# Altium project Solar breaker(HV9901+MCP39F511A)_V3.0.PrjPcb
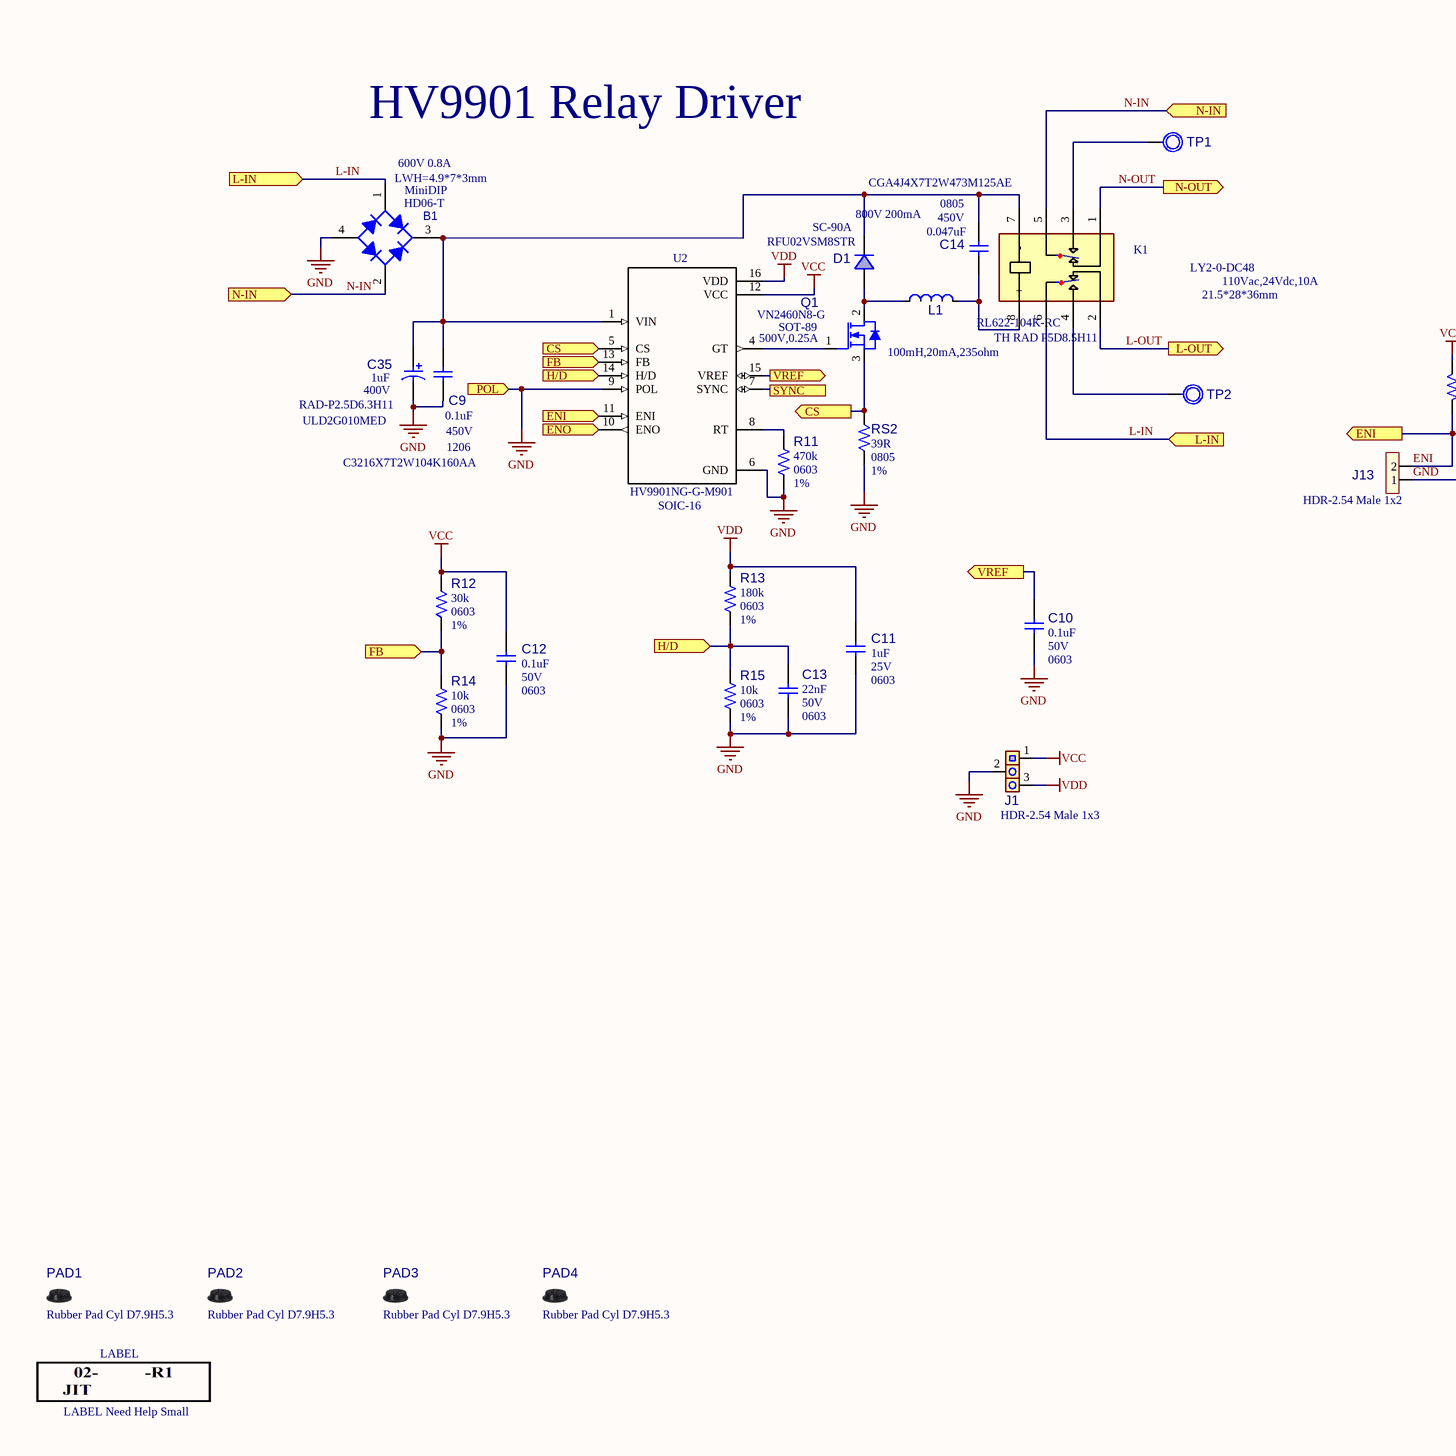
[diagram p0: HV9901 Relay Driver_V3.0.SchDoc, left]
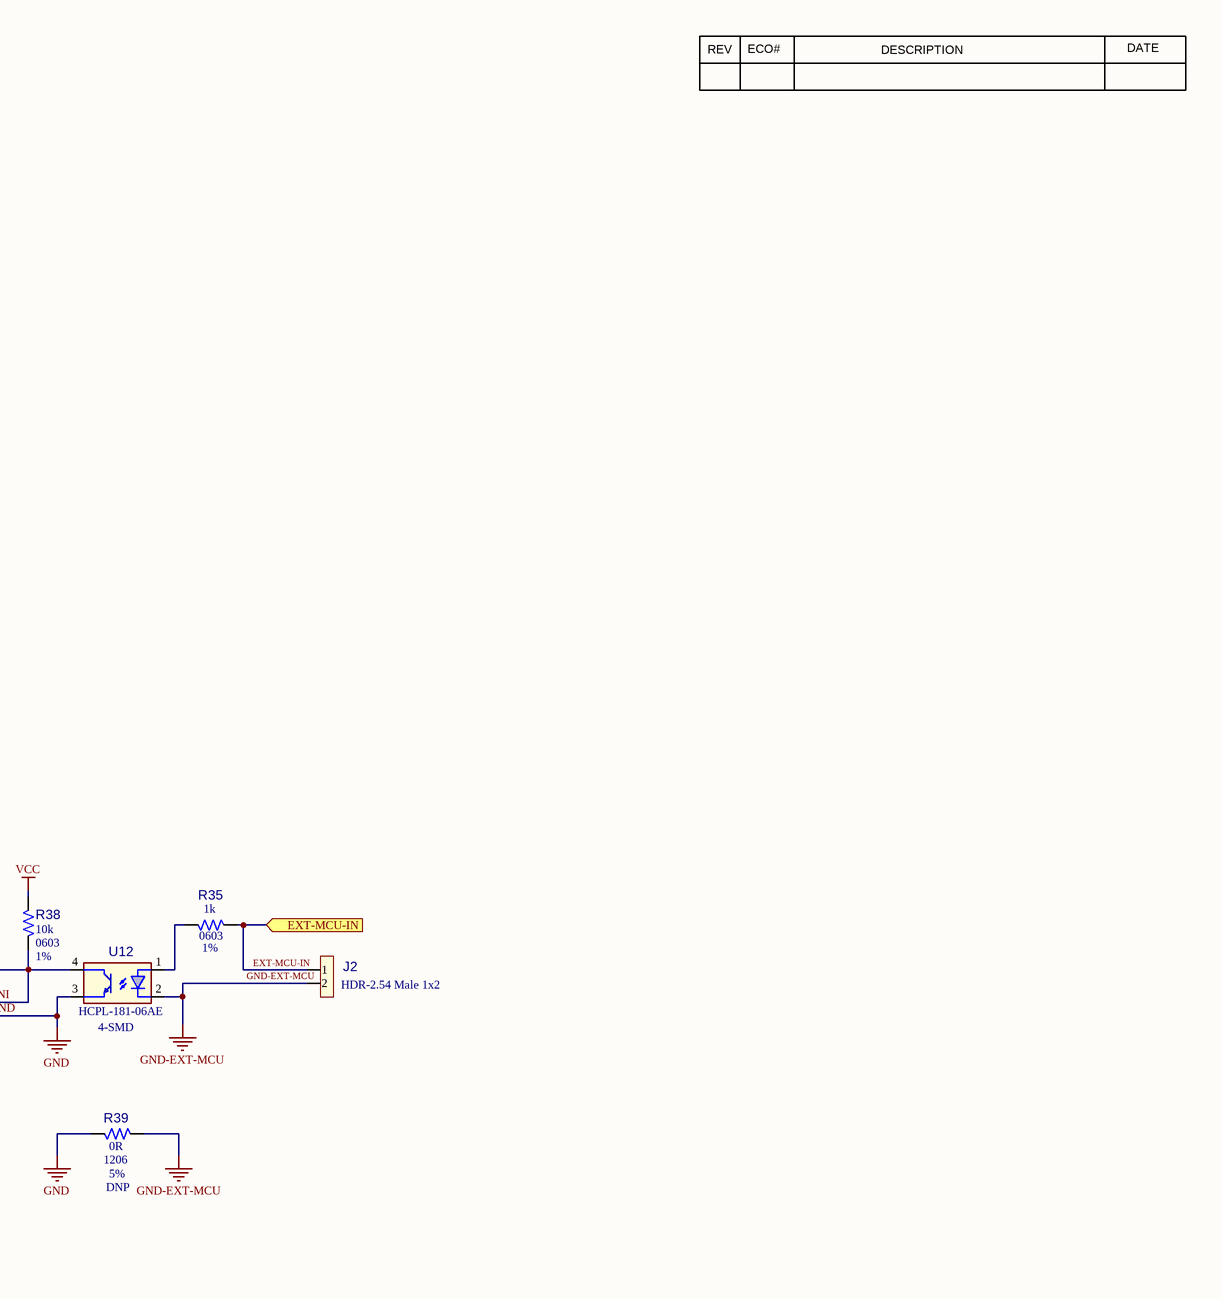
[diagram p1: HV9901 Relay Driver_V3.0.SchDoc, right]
ProjectRevisionART: 3; ProjectPCBNumber: Solar breaker(HV9901+MCP39F511A); ProjectRevisionAssy: 3; ProjectPCBAssyNumber: Solar breaker(HV9901+MCP39F511A)
2 sheets, 133 parts. Net scope: flat (ports and power ports of the same name join across sheets).
Board file: Solar breaker(HV9901+MCP39F511A)_V3.0.PcbDoc
Sheets:
  HV9901 Relay Driver_V3.0.SchDoc
  MCP39F511A Power Monitoring_V3.0.SchDoc

## Sheet HV9901 Relay Driver_V3.0.SchDoc
size A3; CompanyName: Microchip Technology Inc.; Organization: Microchip Technology; Address1: 2355 West Chandler Blvd.; Address2: Chandler, AZ  85224; Address4: USA; SheetTitle: **; PageSetup: Record=PageOptions¦CenterHorizontal=True¦CenterVertical=True¦PrintScale=0.52¦XCorrection=1.00¦YCorrection=1.00¦PrintKind=1¦BorderSize=5000000¦LeftOffset=0¦BottomOffset=0¦Orientation=2¦PaperLength=1000¦PaperWidth=1000¦Scale=100¦PaperSource=7¦PrintQuality=-3¦MediaType=1¦DitherType=10¦PrintScaleMode=1¦PaperKind=A4¦PaperIndex=9

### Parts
B1  B?  [HD01-HD06,DIODES,BRIDGE RECTIFIER]  (value not drawn)
C9  value 0.1uF  Voltage: 450V  Package: 1206  [CAP_C_1206]  (hidden comment: Capacitor NP)
C10  value 0.1uF  Voltage: 50V  Package: 0603  [CAP_C_0603]  (hidden comment: Capacitor NP)
C11  value 1uF  Voltage: 25V  Package: 0603  [CAP_C_0603]  (hidden comment: Capacitor NP)
C12  value 0.1uF  Voltage: 50V  Package: 0603  [CAP_C_0603]  (hidden comment: Capacitor NP)
C13  value 22nF  Voltage: 50V  Package: 0603  [CAP_C_0603]  (hidden comment: Capacitor NP)
C14  value 0.047uF  Voltage: 450V  Package: 0805  [CAP_C_0805]  (hidden comment: Capacitor NP)
C35  value 1uF  Voltage: 400V  Package: RAD-P2.5D6.3H11  [CAP_RAD_P2.5D6.3H11.2]  (hidden comment: Capacitor POL)
D1  value RFU02VSM8STR  [SC-90A]  (hidden comment: Diode Single)
J1  value HDR-2.54 Male 1x3  [HDR_M_2.54_1x3]  (hidden comment: Header 1x3)
J2  value HDR-2.54 Male 1x2  [HDR_M_2.54_1x2]  (hidden comment: Header 1x2)
J13  value HDR-2.54 Male 1x2  [HDR_M_2.54_1x2]  (hidden comment: Header 1x2)
K1  RELAY_LY2-0-DC48_DPDT 10A 48V,2Poles,THD  [RELAY_LY2-0-DC48_DPDT 10A 48V,2Poles,THD]  (value not drawn)
L1  value 100mH,20mA,235ohm  [IND_WE-TI-8055_P5D8.5H5.5]  (hidden comment: Inductor)
LABEL  value LABEL Need Help Small  [LABEL_Need_Help_Small]  (hidden comment: LABEL_Need_Help_Small)
PAD1  value Rubber Pad Cyl D7.9H5.3  [BUMP_3M_SJ61A11_CYLINDRICAL_BLACK_D7.9H5.3]  (hidden comment: Rubber Pad Cylindrical)
PAD2  value Rubber Pad Cyl D7.9H5.3  [BUMP_3M_SJ61A11_CYLINDRICAL_BLACK_D7.9H5.3]  (hidden comment: Rubber Pad Cylindrical)
PAD3  value Rubber Pad Cyl D7.9H5.3  [BUMP_3M_SJ61A11_CYLINDRICAL_BLACK_D7.9H5.3]  (hidden comment: Rubber Pad Cylindrical)
PAD4  value Rubber Pad Cyl D7.9H5.3  [BUMP_3M_SJ61A11_CYLINDRICAL_BLACK_D7.9H5.3]  (hidden comment: Rubber Pad Cylindrical)
Q1  value VN2460N8-G  Package: SOT-89  [SOT-89-3]  (hidden comment: Transistor MOS-N GDS)
R11  value 470k  Package: 0603  Tolerance: 1%  [RES_C_0603]  (hidden comment: Resistor)
R12  value 30k  Package: 0603  Tolerance: 1%  [RES_C_0603]  (hidden comment: Resistor)
R13  value 180k  Package: 0603  Tolerance: 1%  [RES_C_0603]  (hidden comment: Resistor)
R14  value 10k  Package: 0603  Tolerance: 1%  [RES_C_0603]  (hidden comment: Resistor)
R15  value 10k  Package: 0603  Tolerance: 1%  [RES_C_0603]  (hidden comment: Resistor)
R35  value 1k  Package: 0603  Tolerance: 1%  [RES_C_0603]  (hidden comment: Resistor)
R38  value 10k  Package: 0603  Tolerance: 1%  [RES_C_0603]  (hidden comment: Resistor)
R39  value 0R  Package: 1206  [RES_C_1206]  (hidden comment: Resistor)
RS2  value 39R  Package: 0805  Tolerance: 1%  [RES_C_0805]  (hidden comment: Resistor)
TP1  Test Point  [CON_TP_TH_V_WHT_KEC_5002]  (value not drawn)
TP2  Test Point  [CON_TP_TH_V_WHT_KEC_5002]  (value not drawn)
U2  HV9901NG-G-M901  [*SOIC127P600X175-14N]
U12  value HCPL-181-06AE  Package: 4-SMD  [4-SMD_200mil]  (hidden comment: Photocoupler Transistor Out)

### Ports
CS (in), CS (out), ENI (in), ENI (out), ENO (in), EXT-MCU-IN (in), FB (in), H/D (in), L-IN (in), L-OUT (out), N-IN (in), N-OUT (out), POL (in), SYNC (in), VREF (out)

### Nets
GND: B1.4(C) C9.1 C10.1 C11.2 C12.2 C13.1 C35.2 J1.2 J13.1 R11.1 R14.1 R15.1 R39.2 RS2.1 U2.6(GND) U2.9(POL) U12.3(Emitter) ; port POL
GND-EXT-MCU: J2.2 R39.1 U12.2(Cathode)
VCC: C12.1 J1.1 R12.2 R38.2 U2.12(VCC)
VDD: C11.1 J1.3 R13.2 U2.16(VDD)
ENI: J13.2 R38.1 U2.11(ENI) U12.4(Collector) ; port ENI
EXT-MCU-IN: J2.1 R35.1 ; port EXT-MCU-IN
L-IN: B1.1(K) K1.6 ; port L-IN
L-OUT: K1.2 ; port L-OUT
N-IN: B1.2(A) K1.5 ; port N-IN
N-OUT: K1.1 ; port N-OUT
NetB1_3: B1.3(C) C9.2 C14.2 C35.1 D1.2(K) K1.7(-) U2.1(VIN)
NetC10_2: C10.2 U2.15(VREF) ; port VREF
NetC13_2: C13.2 R13.1 R15.2 U2.14(H/D) ; port H/D
NetC14_1: C14.1 K1.8(+) L1.2(F)
NetD1_1: D1.1(A) L1.1(S) Q1.2(D)
NetK1_3: K1.3 TP1.1
NetK1_4: K1.4 TP2.1
NetQ1_1: Q1.1(G) U2.4(GT)
NetQ1_3: Q1.3(S) RS2.2 U2.5(CS) ; port CS
NetR11_2: R11.2 U2.8(RT)
NetR12_1: R12.1 R14.2 U2.13(FB) ; port FB
NetR35_2: R35.2 U12.1(Anode)
NetU2_10: U2.10(ENO) ; port ENO

Not connected (* = marked no-connect by the designer): U2 7(SYNC)

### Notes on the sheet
- REV
- ECO#
- DESCRIPTION
- DATE
- HV9901 Relay Driver
- (near B1) LWH=4.9*7*3mm
- (near B1) 600V 0.8A
- (near B1) HD06-T
- (near B1) MiniDIP
- (near D1) 800V 200mA
- CGA4J4X7T2W473M125AE
- (near K1) LY2-0-DC48
- (near K1) 110Vac,24Vdc,10A
- 500V,0.25A
- (near L1) RL622-104K-RC
- TH RAD P5D8.5H11
- (near K1) 21.5*28*36mm
- ULD2G010MED
- C3216X7T2W104K160AA
- (near U2) SOIC-16
- (near R39) DNP
- (near R39) 5%

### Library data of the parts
C9 = CAP1426: Capacitor; Manufacturer 1: Johanson Dielectrics Inc; Manufacturer Part Number 1: 501R18W223KV4E; Description_: CAP CER 0.022uF 500V 10% X7R SMD 1206; Dev Tools Status: Production; Tolerance: 10%; Type: Ceramic; Owner: Jamus Griego; Populated: YES
C10-C13 = CAP0012: Capacitor; Manufacturer 1: Cal-Chip; Manufacturer Part Number 1: GMC10Y5V104Z25NTLF; Description_: CAP CER 0.1uF 25V 20% Y5V SMD 0603; Dev Tools Status: Production; Tolerance: 20%; Temperature Coeffcient: Y5V; Type: Ceramic; Populated: Yes
C14 = CAP2158: Capacitor; Manufacturer 1: TDK Corporation; Manufacturer Part Number 1: CGA4F4X7T2W103M085AE; Description_: CAP CER 10000pF 450V 10% X7T SMD 0805; Dev Tools Status: Design; Tolerance: 10%; Type: Ceramic; Owner: Cristian Papuc; Populated: YES; Temperature Coeffcient: X7T
C35 = CAP1007: Capacitor
D1 = DIODE1422: Manufacturer 1: Panasonic; Manufacturer Part Number 1: DA2JF2300L; Description_: DIO DA2JF2300L SWITCHING 1.25V 0.3A 300V SC-90A; Dev Tools Status: Design; Type: Rectifier Single; Forward Current: 0.3A; Populated: YES; Owner: Iulian Margarit; Reverse Current: 1uA; Reverse Voltage: 300V
J1 = CON1105: Manufacturer 1: FCI; Manufacturer Part Number 1: 68000-103HLF; Description_: CON HDR-2.54 Male 1x3 Gold 5.84MH TH VERT; Dev Tools Status: Production; Owner: Bogdan P (M91398); Populated: Yes
J2 J13 = CON1108: Manufacturer 1: FCI; Manufacturer Part Number 1: 77311-118-02LF; Description_: CON HDR-2.54 Male 1x2 Gold 5.84MH TH VERT; Dev Tools Status: Production; Owner: Bogdan P (M91398); Populated: Yes
L1 = IND1323: Manufacturer 1: Wurth Electronics Inc; Manufacturer Part Number 1: 7447412681; Description_: INDUCTOR 680uH 330mA 10% TH RAD P5D8.5H5.5; Dev Tools Status: Design; Owner: Catalin Modoran; DCR: 4R; Saturation Current: 350mA; RMS Current: 330mA; Test Frequency: 1kHz; Populated: YES
LABEL = 08-00028: Description_: LABEL, ASSY W/REV LEVEL (SMALL MODULES) PER MTS-0002; Dev Tools Status: Production; Populated: MECH
PAD1-PAD4 = MISC1024: Manufacturer 1: 3M; Manufacturer Part Number 1: SJ61A11; Description_: MECH HW RUBBER PAD CYLINDRICAL D7.9 H5.3 BLACK; Dev Tools Status: Production; Owner: Bogdan Popescu; Populated: MECH
Q1 = TRA1253: Transistor MOS; Manufacturer 1: Microchip Technology; Description_: TRANS FET N-CH VN2460N8-G 600V 200mA 1.6W SOT-89; Dev Tools Status: Design; Type: FET; Current: 200mA; Drain to Source Voltage: 600V; Gate to Source Voltage: 20V; Power: 1.6W; Owner: Cristian Papuc; Populated: YES
R11-R15 R35 R38 = RSMT0138: Manufacturer 1: Panasonic; Manufacturer Part Number 1: ERJ-3EKF1001V; Description_: RES TKF 1k 1% 1/10W SMD 0603; Dev Tools Status: Production; Voltage: 75V; Temperature Coeffcient: 100ppm/C; Power: 1/10W; Populated: Yes
R39 = RES2320: Manufacturer 1: Panasonic Electronic Components; Manufacturer Part Number 1: ERJ-8GEY0R00V; Description_: RES TKF 0R SMD 1206 AEC-Q200; Dev Tools Status: Design; Populated: YES; Current: 2A; Owner: Gabor Bihari
RS2 = RSMT0248: Manufacturer 1: Stackpole Electronics Inc; Manufacturer Part Number 1: RMCF-1/10-39-1%; Description_: RES TKF 39R 1% 1/8W SMD 0805; Dev Tools Status: Production; Voltage: 150V; Temperature Coeffcient: 100ppm/C; Power: 1/8W; Populated: Yes
TP1 TP2 = MISC0028: Manufacturer 1: Keystone; Manufacturer Part Number 1: 5002; Value: TP LOOP White; Description_: MISC, TEST POINT MULTI PURPOSE MINI WHITE; Dev Tools Status: Production
U2 = HV9901NG-G-M901: HV9901 Series 10 to 450V 1 mA 750 mW Universal Relay Driver - SOIC-16N; MF: Microchip
U12 = IC1119: Photocoupler; Manufacturer 1: Avago Technologies; Manufacturer Part Number 1: HCPL-181-00CE; MCHP-ID: IC1119; Description_: IC PHOTO HCPL-181 4-SMD; Dev Tools Status: Production; Owner: Bogdan P (M91398); Populated: Yes

## Sheet MCP39F511A Power Monitoring_V3.0.SchDoc
size A3; CompanyName: Microchip Technology Inc.; Organization: Microchip Technology; Address1: 2355 West Chandler Blvd.; Address2: Chandler, AZ  85224; Address4: USA; SheetTitle: **; PageSetup: Record=PageOptions¦CenterHorizontal=True¦CenterVertical=True¦PrintScale=0.52¦XCorrection=1.00¦YCorrection=1.00¦PrintKind=1¦BorderSize=5000000¦LeftOffset=0¦BottomOffset=0¦Orientation=2¦PaperLength=1000¦PaperWidth=1000¦Scale=100¦PaperSource=7¦PrintQuality=-3¦MediaType=1¦DitherType=10¦PrintScaleMode=1¦PaperKind=A4¦PaperIndex=9
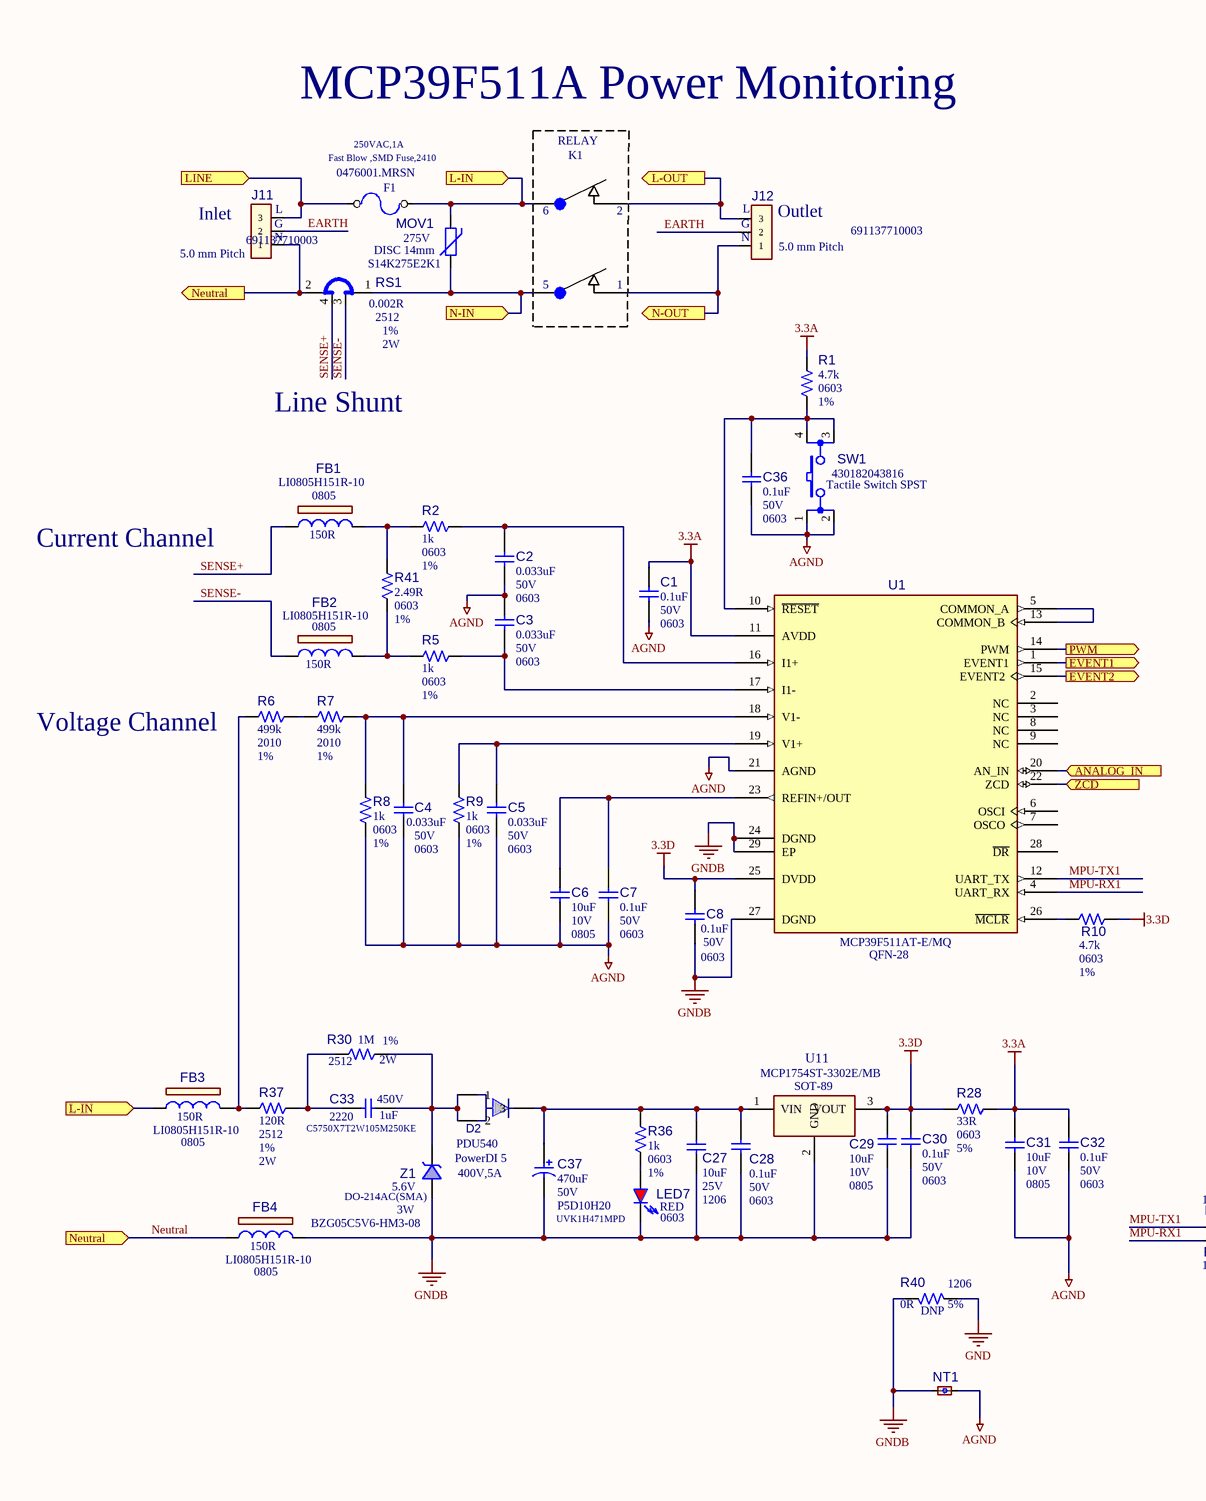
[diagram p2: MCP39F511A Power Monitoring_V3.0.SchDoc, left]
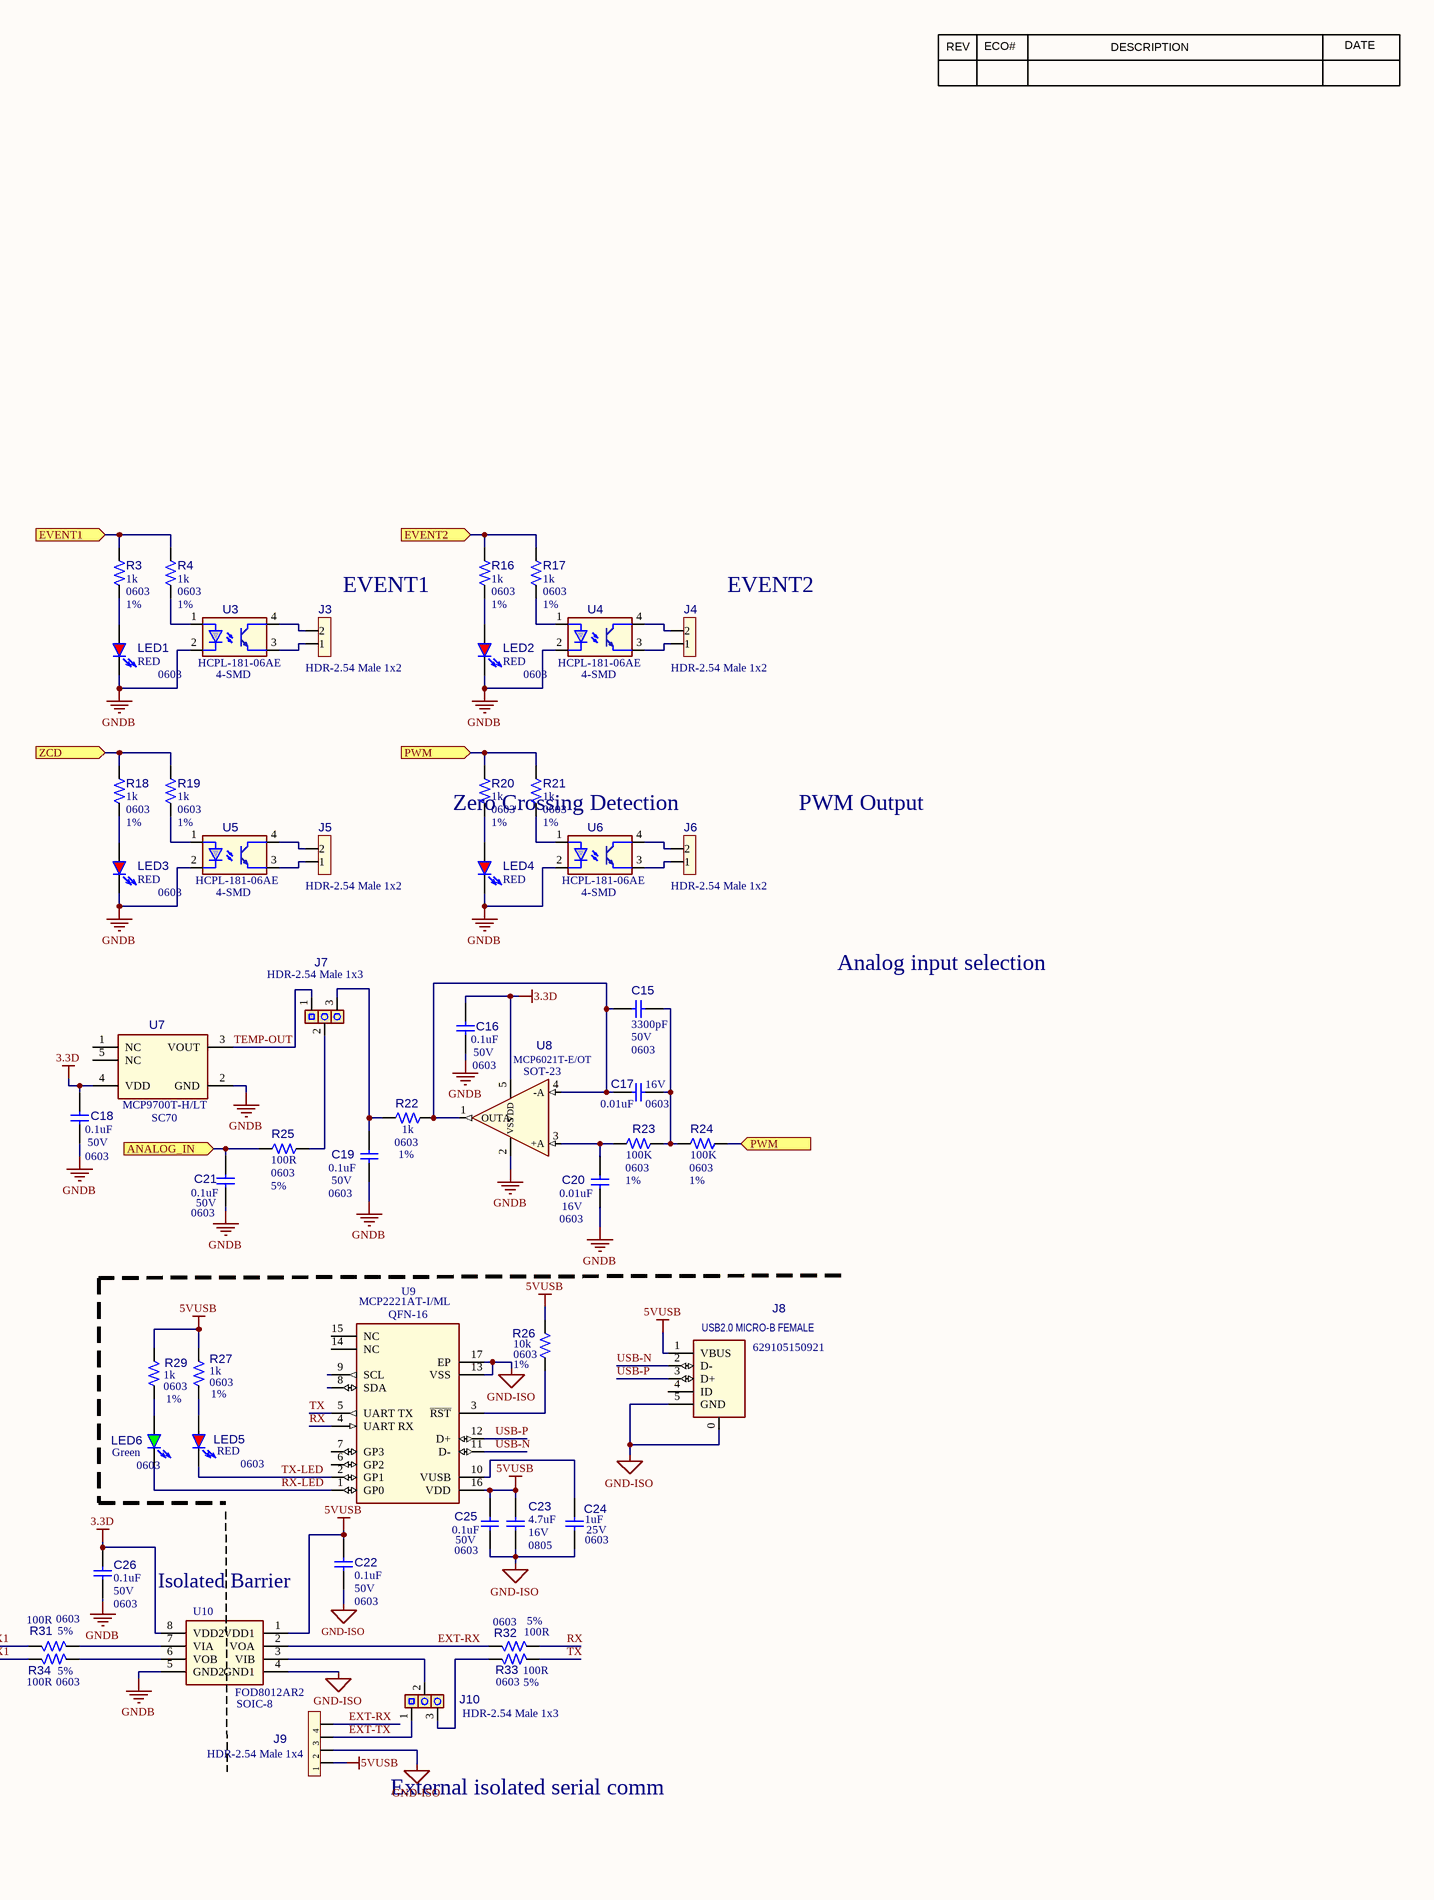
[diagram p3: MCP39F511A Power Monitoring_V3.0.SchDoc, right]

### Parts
C1  value 0.1uF  Voltage: 50V  Package: 0603  [CAP_C_0603]  (hidden comment: Capacitor NP)
C2  value 0.033uF  Voltage: 50V  Package: 0603  [CAP_C_0603]  (hidden comment: Capacitor NP)
C3  value 0.033uF  Voltage: 50V  Package: 0603  [CAP_C_0603]  (hidden comment: Capacitor NP)
C4  value 0.033uF  Voltage: 50V  Package: 0603  [CAP_C_0603]  (hidden comment: Capacitor NP)
C5  value 0.033uF  Voltage: 50V  Package: 0603  [CAP_C_0603]  (hidden comment: Capacitor NP)
C6  value 10uF  Voltage: 10V  Package: 0805  [CAP_C_0805]  (hidden comment: Capacitor NP)
C7  value 0.1uF  Voltage: 50V  Package: 0603  [CAP_C_0603]  (hidden comment: Capacitor NP)
C8  value 0.1uF  Voltage: 50V  Package: 0603  [CAP_C_0603]  (hidden comment: Capacitor NP)
C15  value 3300pF  Voltage: 50V  Package: 0603  [CAP_C_0603]  (hidden comment: Capacitor NP)
C16  value 0.1uF  Voltage: 50V  Package: 0603  [CAP_C_0603]  (hidden comment: Capacitor NP)
C17  value 0.01uF  Voltage: 16V  Package: 0603  [CAP_C_0603]  (hidden comment: Capacitor NP)
C18  value 0.1uF  Voltage: 50V  Package: 0603  [CAP_C_0603]  (hidden comment: Capacitor NP)
C19  value 0.1uF  Voltage: 50V  Package: 0603  [CAP_C_0603]  (hidden comment: Capacitor NP)
C20  value 0.01uF  Voltage: 16V  Package: 0603  [CAP_C_0603]  (hidden comment: Capacitor NP)
C21  value 0.1uF  Voltage: 50V  Package: 0603  [CAP_C_0603]  (hidden comment: Capacitor NP)
C22  value 0.1uF  Voltage: 50V  Package: 0603  [CAP_C_0603]  (hidden comment: Capacitor NP)
C23  value 4.7uF  Voltage: 16V  Package: 0805  [CAP_C_0805]  (hidden comment: Capacitor NP)
C24  value 1uF  Voltage: 25V  Package: 0603  [CAP_C_0603]  (hidden comment: Capacitor NP)
C25  value 0.1uF  Voltage: 50V  Package: 0603  [CAP_C_0603]  (hidden comment: Capacitor NP)
C26  value 0.1uF  Voltage: 50V  Package: 0603  [CAP_C_0603]  (hidden comment: Capacitor NP)
C27  value 10uF  Voltage: 25V  Package: 1206  [CAP_C_1206]  (hidden comment: Capacitor NP)
C28  value 0.1uF  Voltage: 50V  Package: 0603  [CAP_C_0603]  (hidden comment: Capacitor NP)
C29  value 10uF  Voltage: 10V  Package: 0805  [CAP_C_0805]  (hidden comment: Capacitor NP)
C30  value 0.1uF  Voltage: 50V  Package: 0603  [CAP_C_0603]  (hidden comment: Capacitor NP)
C31  value 10uF  Voltage: 10V  Package: 0805  [CAP_C_0805]  (hidden comment: Capacitor NP)
C32  value 0.1uF  Voltage: 50V  Package: 0603  [CAP_C_0603]  (hidden comment: Capacitor NP)
C33  value 1uF  Voltage: 450V  Package: 2220  [CAP_C_2220_Stack-2]  (hidden comment: Capacitor NP)
C36  value 0.1uF  Voltage: 50V  Package: 0603  [CAP_C_0603]  (hidden comment: Capacitor NP)
C37  value 470uF  Voltage: 50V  Package: P5D10H20  [CAP_RAD_P5D10H20]  (hidden comment: Capacitor POL)
D2  PowerDI5_Diode  [PowerDI5_Diode]  (value not drawn)
F1  Fuse_476 series fuse (Littelfuse)_2410  [Fuse_476 series fuse (Littelfuse)_2410]  (value not drawn)
FB1  value 150R  Package: 0805  Manufacturer Part Number 1: LI0805H151R-10  [IND_C_0805]  (hidden comment: Ferrite Bead)
FB2  value 150R  Package: 0805  Manufacturer Part Number 1: LI0805H151R-10  [IND_C_0805]  (hidden comment: Ferrite Bead)
FB3  value 150R  Package: 0805  Manufacturer Part Number 1: LI0805H151R-10  [IND_C_0805]  (hidden comment: Ferrite Bead)
FB4  value 150R  Package: 0805  Manufacturer Part Number 1: LI0805H151R-10  [IND_C_0805]  (hidden comment: Ferrite Bead)
J3  value HDR-2.54 Male 1x2  [HDR_M_2.54_1x2]  (hidden comment: Header 1x2)
J4  value HDR-2.54 Male 1x2  [HDR_M_2.54_1x2]  (hidden comment: Header 1x2)
J5  value HDR-2.54 Male 1x2  [HDR_M_2.54_1x2]  (hidden comment: Header 1x2)
J6  value HDR-2.54 Male 1x2  [HDR_M_2.54_1x2]  (hidden comment: Header 1x2)
J7  value HDR-2.54 Male 1x3  [HDR_M_2.54_1x3]  (hidden comment: Header 1x3)
J8  value USB2.0 MICRO-B FEMALE  [USB2.0 Micro-B female connector-compatible with 629105150921,629105136821,C8359-05ZFDXNBNR]  (hidden comment: USB2.0 Micro-B female connector-compatible with 629105150921,629105136821,C8359-05ZFDXNBNR)
J9  value HDR-2.54 Male 1x4  [HDR_M_2.54_1x4]  (hidden comment: Header 1x4)
J10  value HDR-2.54 Male 1x3  [HDR_M_2.54_1x3]  (hidden comment: Header 1x3)
J11  Value2: Inlet  [CON_TERMINAL_5_1x3_TH_RA_WE_691137710003]  (hidden comment: Header 1x1)
J12  Value2: Outlet  [CON_TERMINAL_5_1x3_TH_RA_WE_691137710003]  (hidden comment: Header 1x1)
LED1  value RED  [LED_0603_RED]  (hidden comment: LED_red)
LED2  value RED  [LED_0603_RED]  (hidden comment: LED_red)
LED3  value RED  [LED_0603_RED]  (hidden comment: LED_red)
LED4  value RED  [LED_0603_RED]  (hidden comment: LED_red)
LED5  value RED  [LED_0603_RED]  (hidden comment: LED_red)
LED6  value Green  [LED_0603_GREEN]  (hidden comment: LED_green)
LED7  value RED  [LED_0603_RED]  (hidden comment: LED_red)
MOV1  value 275V  Package: DISC 14mm  Manufacturer Part Number 1: S14K275E2K1  [MOV_EPC_S14KXX]  (hidden comment: Varistor)
NT1  Net Tie  [NET_TIE_0.2mm]  (value not drawn)  (net tie, no BOM)
R1  value 4.7k  Package: 0603  Tolerance: 1%  [RES_C_0603]  (hidden comment: Resistor)
R2  value 1k  Package: 0603  Tolerance: 1%  [RES_C_0603]  (hidden comment: Resistor)
R3  value 1k  Package: 0603  Tolerance: 1%  [RES_C_0603]  (hidden comment: Resistor)
R4  value 1k  Package: 0603  Tolerance: 1%  [RES_C_0603]  (hidden comment: Resistor)
R5  value 1k  Package: 0603  Tolerance: 1%  [RES_C_0603]  (hidden comment: Resistor)
R6  value 499k  Package: 2010  Tolerance: 1%  [RES_C_2010]  (hidden comment: Resistor)
R7  value 499k  Package: 2010  Tolerance: 1%  [RES_C_2010]  (hidden comment: Resistor)
R8  value 1k  Package: 0603  Tolerance: 1%  [RES_C_0603]  (hidden comment: Resistor)
R9  value 1k  Package: 0603  Tolerance: 1%  [RES_C_0603]  (hidden comment: Resistor)
R10  value 4.7k  Package: 0603  Tolerance: 1%  [RES_C_0603]  (hidden comment: Resistor)
R16  value 1k  Package: 0603  Tolerance: 1%  [RES_C_0603]  (hidden comment: Resistor)
R17  value 1k  Package: 0603  Tolerance: 1%  [RES_C_0603]  (hidden comment: Resistor)
R18  value 1k  Package: 0603  Tolerance: 1%  [RES_C_0603]  (hidden comment: Resistor)
R19  value 1k  Package: 0603  Tolerance: 1%  [RES_C_0603]  (hidden comment: Resistor)
R20  value 1k  Package: 0603  Tolerance: 1%  [RES_C_0603]  (hidden comment: Resistor)
R21  value 1k  Package: 0603  Tolerance: 1%  [RES_C_0603]  (hidden comment: Resistor)
R22  value 1k  Package: 0603  Tolerance: 1%  [RES_C_0603]  (hidden comment: Resistor)
R23  value 100K  Package: 0603  Tolerance: 1%  [RES_C_0603]  (hidden comment: Resistor)
R24  value 100K  Package: 0603  Tolerance: 1%  [RES_C_0603]  (hidden comment: Resistor)
R25  value 100R  Package: 0603  Tolerance: 5%  [RES_C_0603]  (hidden comment: Resistor)
R26  value 10k  Package: 0603  Tolerance: 1%  [RES_C_0603]  (hidden comment: Resistor)
R27  value 1k  Package: 0603  Tolerance: 1%  [RES_C_0603]  (hidden comment: Resistor)
R28  value 33R  Package: 0603  Tolerance: 5%  [RES_C_0603]  (hidden comment: Resistor)
R29  value 1k  Package: 0603  Tolerance: 1%  [RES_C_0603]  (hidden comment: Resistor)
R30  value 1M  Package: 2512  Tolerance: 1%  Power: 2W  [RES_C_2512]  (hidden comment: Resistor)
R31  value 100R  Package: 0603  Tolerance: 5%  [RES_C_0603]  (hidden comment: Resistor)
R32  value 100R  Package: 0603  Tolerance: 5%  [RES_C_0603]  (hidden comment: Resistor)
R33  value 100R  Package: 0603  Tolerance: 5%  [RES_C_0603]  (hidden comment: Resistor)
R34  value 100R  Package: 0603  Tolerance: 5%  [RES_C_0603]  (hidden comment: Resistor)
R36  value 1k  Package: 0603  Tolerance: 1%  [RES_C_0603]  (hidden comment: Resistor)
R37  value 120R  Package: 2512  Tolerance: 1%  Power: 2W  [RES_C_2512]  (hidden comment: Resistor)
R40  value 0R  Package: 1206  [RES_C_1206]  (hidden comment: Resistor)
R41  value 2.49R  Package: 0603  Tolerance: 1%  [RES_C_0603]  (hidden comment: Resistor)
RS1  value 0.002R  Package: 2512  Tolerance: 1%  [RES_C_2512_SHUNT]  (hidden comment: Shunt 4 Pin)
SW1  value 430182043816  Symbol: Tactile Switch SPST  [SW_TACT_SMD_B3S-1000]  (hidden comment: Switch 4 Pin)
U1  value MCP39F511AT-E/MQ  [QFN-28_5x5]  (hidden comment: MCP39F511 QFN-28)
U3  value HCPL-181-06AE  Package: 4-SMD  [4-SMD_200mil]  (hidden comment: Photocoupler Transistor Out)
U4  value HCPL-181-06AE  Package: 4-SMD  [4-SMD_200mil]  (hidden comment: Photocoupler Transistor Out)
U5  value HCPL-181-06AE  Package: 4-SMD  [4-SMD_200mil]  (hidden comment: Photocoupler Transistor Out)
U6  value HCPL-181-06AE  Package: 4-SMD  [4-SMD_200mil]  (hidden comment: Photocoupler Transistor Out)
U7  value MCP9700T-H/LT  PackageType: SC70  [SC-70-5]  (hidden comment: MCP9700(A)_1(A) SC-70-5)
U8  value MCP6021T-E/OT  PackageType: SOT-23  [SOT-23-5]  (hidden comment: MCP6XX1_6 SOT-23-5_SC-70-5)
U9  value MCP2221AT-I/ML  Symbol: QFN-16  [QFN-16_4X4_EP2.5X2.5]  (hidden comment: MCP2221 QFN-16)
U10  value FOD8012AR2  [SOIC-8]  (hidden comment: FOD8012)
U11  value MCP1754ST-3302E/MB  PackageType: SOT-89  [SOT-89-3]  (hidden comment: MCP1754S SOT-89-3_SOT-223-3)
Z1  value 5.6V  Package: DO-214AC(SMA)  Power: 3W  [DO-214AC_SMA]  (hidden comment: Diode Zener)

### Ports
ANALOG_IN (in), EVENT1 (in), EVENT1 (out), EVENT2 (in), EVENT2 (out), L-IN (in), L-OUT (out), LINE (in), N-IN (in), N-OUT (out), Neutral (in), Neutral (out), PWM (in), PWM (out), ZCD (in)

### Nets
3.3A: C1.2 C31.2 C32.2 R1.2 R28.1 U1.11(AVDD)
3.3D: C8.2 C16.2 C18.2 C26.1 C29.2 C30.2 R10.1 R28.2 U1.25(DVDD) U7.4(VDD) U8.5(VDD) U10.8(VDD2) U11.3(VOUT)
5VUSB: C22.1 C23.2 C25.1 J8.1(VBUS) J9.1 R26.2 R27.2 R29.2 U9.16(VDD) U10.1(VDD1)
AGND: C1.1 C2.1 C3.2 C4.1 C5.1 C6.1 C7.1 C31.1 C32.1 C36.1 NT1.1 R8.1 R9.1 SW1.1 SW1.2 U1.21(AGND)
GND: R40.1
GND-ISO: C22.2 C23.1 C24.2 C25.2 J8.0(SHLD) J8.5(GND) J9.2 U9.13(VSS) U9.17(EP) U10.4(GND1)
GNDB: C8.1 C16.1 C18.1 C19.1 C20.1 C21.1 C26.2 C27.1 C28.1 C29.1 C30.1 C37.2 FB4.2 LED1.2(K) LED2.2(K) LED3.2(K) LED4.2(K) LED7.2(K) NT1.2 R40.2 U1.24(DGND) U1.27(DGND) U1.29(EP) U3.2(Cathode) U4.2(Cathode) U5.2(Cathode) U6.2(Cathode) U7.2(GND) U8.2(VSS) U10.5(GND2) U11.2(GND) Z1.1(A)
EARTH: J11.2 J12.2
EXT-RX: J9.4 R32.1 U10.2(VOA)
EXT-TX: J9.3 J10.1
L-IN: F1.1 FB3.1 MOV1.2 ; port L-IN
L-OUT: J12.3 ; port L-OUT
MPU-RX1: R34.1 U1.4(UART_RX)
MPU-TX1: R31.1 U1.12(UART_TX)
N-IN: MOV1.1 RS1.1 ; port N-IN
N-OUT: J12.1 ; port N-OUT
Neutral: FB4.1 J11.1 RS1.2 ; port Neutral
RX: R32.2 U9.4(UART_RX)
RX-LED: LED6.2(K) U9.1(GP0)
SENSE+: FB1.1 RS1.4
SENSE-: FB2.1 RS1.3
TEMP-OUT: J7.1 U7.3(VOUT)
TX: R33.2 U9.5(UART_TX)
TX-LED: LED5.2(K) U9.2(GP1)
USB-N: J8.2(D-) U9.11(D-)
USB-P: J8.3(D+) U9.12(D+)
NetC2_2: C2.2 R2.1 U1.16(I1+)
NetC3_1: C3.1 R5.1 U1.17(I1-)
NetC4_2: C4.2 R7.2 R8.2 U1.18(V1-)
NetC5_2: C5.2 R9.2 U1.19(V1+)
NetC6_2: C6.2 C7.2 U1.23(REFIN+/OUT)
NetC15_1: C15.1 C17.1 R23.1 R24.2
NetC15_2: C15.2 C17.2 R22.1 U8.1(OUTA) U8.4(-A)
NetC19_2: C19.2 J7.3 R22.2
NetC20_2: C20.2 R23.2 U8.3(+A)
NetC21_2: C21.2 R25.2 U1.20(AN_IN) ; port ANALOG_IN
NetC24_1: C24.1 U9.10(VUSB)
NetC27_2: C27.2 C28.2 C37.1 D2.3 R36.2 U11.1(VIN)
NetC33_1: C33.1 R30.2 R37.1
NetC33_2: C33.2 D2.1 D2.2 R30.1 Z1.2(K)
NetC36_2: C36.2 R1.1 SW1.3 SW1.4 U1.10(~{RESET})
NetF1_2: F1.2 J11.3 ; port LINE
NetFB1_2: FB1.2 R2.2 R41.1
NetFB2_2: FB2.2 R5.2 R41.2
NetFB3_2: FB3.2 R6.1 R37.2
NetJ3_1: J3.1 U3.3(Emitter)
NetJ3_2: J3.2 U3.4(Collector)
NetJ4_1: J4.1 U4.3(Emitter)
NetJ4_2: J4.2 U4.4(Collector)
NetJ5_1: J5.1 U5.3(Emitter)
NetJ5_2: J5.2 U5.4(Collector)
NetJ6_1: J6.1 U6.3(Emitter)
NetJ6_2: J6.2 U6.4(Collector)
NetJ7_2: J7.2 R25.1
NetJ10_2: J10.2 U10.3(VIB)
NetJ10_3: J10.3 R33.1
NetLED1_1: LED1.1(A) R3.1
NetLED2_1: LED2.1(A) R16.1
NetLED3_1: LED3.1(A) R18.1
NetLED4_1: LED4.1(A) R20.1
NetLED5_1: LED5.1(A) R27.1
NetLED6_1: LED6.1(A) R29.1
NetLED7_1: LED7.1(A) R36.1
NetR3_2: R3.2 R4.2 U1.1(EVENT1) ; port EVENT1
NetR4_1: R4.1 U3.1(Anode)
NetR6_2: R6.2 R7.1
NetR10_2: R10.2 U1.26(~{MCLR})
NetR16_2: R16.2 R17.2 U1.15(EVENT2) ; port EVENT2
NetR17_1: R17.1 U4.1(Anode)
NetR18_2: R18.2 R19.2 U1.22(ZCD) ; port ZCD
NetR19_1: R19.1 U5.1(Anode)
NetR20_2: R20.2 R21.2 R24.1 U1.14(PWM) ; port PWM
NetR21_1: R21.1 U6.1(Anode)
NetR26_1: R26.1 U9.3(~{RST})
NetR31_2: R31.2 U10.7(VIA)
NetR34_2: R34.2 U10.6(VOB)
NetU1_5: U1.5(COMMON_A) U1.13(COMMON_B)

Not connected (* = marked no-connect by the designer): J8 4(ID); U1 2(NC) 3(NC) 6(OSCI) 7(OSCO) 8(NC) 9(NC) 28(~{DR}); U7 1(NC) 5(NC); U9 6(GP2) 7(GP3) 8(SDA) 9(SCL) 14(NC) 15(NC)

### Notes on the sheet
- REV
- ECO#
- DESCRIPTION
- DATE
- MCP39F511A Power Monitoring
- (near F1) Fast Blow ,SMD Fuse,2410
- (near F1) 0476001.MRSN
- (near F1) 250VAC,1A
- RELAY
- K1
- EVENT1
- EVENT2
- (near J11) 691137710003
- (near J11) G
- (near J11) N
- (near J11) L
- 6
- 2
- (near J12) G
- (near J12) N
- (near J12) L
- (near J12) 691137710003
- (near LED1) 0603
- (near LED2) 0603
- (near J11) 5.0 mm Pitch
- 5
- 1
- (near J12) 5.0 mm Pitch
- 2W
- Zero Crossing Detection
- (near J6) PWM Output
- Line Shunt
- (near LED3) 0603
- Current Channel
- (near C15) Analog input selection
- (near R6) Voltage Channel
- (near J8) 629105150921
- (near U1) QFN-28
- (near LED6) 0603
- (near LED5) 0603
- C5750X7T2W105M250KE
- PowerDI 5
- PDU540
- (near Z1) 400V,5A
- (near C22) Isolated Barrier
- (near FB4) BZG05C5V6-HM3-08
- UVK1H471MPD
- (near LED7) 0603
- (near R40) DNP
- (near R40) 5%
- (near J9) External isolated serial comm

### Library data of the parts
C1 C7 C8 C16 C18 C22 C26 C28 C30 C32 C36 = CAP0012: as C10 on sheet HV9901 Relay Driver_V3.0
C2-C5 C15 C17 C19-C21 = CAP1130: Capacitor; Manufacturer 1: TDK; Manufacturer Part Number 1: C1608X7R1H333K; Description_: CAP CER 0.033uF 50V 10% X7R SMD 0603; Dev Tools Status: Production; Tolerance: 10%; Temperature Coeffcient: X7R; Type: Ceramic; Owner: Bogdan P (M91398); Populated: YES
C6 = CAP0372: Capacitor; Manufacturer 1: Taiyo Yuden; Manufacturer Part Number 1: LMK212BJ106KG-T; Description_: CAP CER 10uF 10V 10% X5R SMD 0805; Dev Tools Status: Production; Tolerance: 10%; Temperature Coeffcient: X5R; Type: Ceramic; Owner: Randolph Sobrepena; Populated: YES
C23 = CAP0419: Capacitor
C24 = CAP1060: Capacitor; Manufacturer 1: TDK Corporation; Manufacturer Part Number 1: CGA3E1X7R1E105K080AC; Description_: CAP CER 1uF 25V 10% X7R SMD 0603; Dev Tools Status: Production; Tolerance: 10%; Temperature Coeffcient: X7R; Type: Ceramic; Populated: YES; Owner: Sompoch Loboonlert
C25 = CAP0011: Capacitor; Manufacturer 1: Wurth Electronics Inc; Manufacturer Part Number 1: 885012206046; Description_: CAP CER 0.1uF 16V 10% X7R SMD 0603; Dev Tools Status: Production; Tolerance: 10%; Temperature Coeffcient: X7R; Type: Ceramic; Populated: Yes
C27 = CAP1159: Capacitor; Manufacturer 1: Murata Electronics North America; Manufacturer Part Number 1: GRM31CR71E106KA12L; Description_: CAP CER 10uF 25V 10% X7R SMD 1206; Dev Tools Status: Production; Tolerance: 10%; Temperature Coeffcient: X7R; Type: Ceramic; Owner: Adrian T (M91397); Populated: Yes
C29 C31 = CAP1979: Capacitor; Manufacturer 1: TDK Corporation; Manufacturer Part Number 1: C2012X7R1A106K125AC; Description_: CAP CER 10uF 10V 10% X7R 0805; Dev Tools Status: Design; Tolerance: 10%; Temperature Coeffcient: X7R; Type: Ceramic; Owner: Dragos Danaila; Populated: YES
C33 = CAP1929: Manufacturer 1: TDK Corporation; Manufacturer Part Number 1: C5750X7T2W105M250KE; Description_: CAP CER 1uF 450V 20% X7T SMD 2220; Dev Tools Status: Production; Tolerance: 20%; Temperature Coeffcient: X7T; Type: Ceramic; Owner: Iulian Margarit; Populated: YES
C37 = CAP1906: Capacitor
FB1-FB4 = IND1114: Manufacturer 1: Laird; Description_: FERRITE 150R@100MHz 800mA SMD 0805; Dev Tools Status: Production; Owner: Bogdan P (M91398); DCR: 0.15R; Saturation Current: 800mA; Populated: Yes
J3-J6 = CON1108: as J2 on sheet HV9901 Relay Driver_V3.0
J7 J10 = CON0465: Manufacturer 1: Samtec; Manufacturer Part Number 1: TSW-103-07-T-S; Description_: CON HDR-2.54 Male 1x3 Tin 5.84MH TH VERT; Dev Tools Status: Production; Populated: Yes
J8 = USB2.0 Micro-B female connector-compatible with 629105150921,629105136821,C8359-05ZFDXNBNR: Manufacturer 1: FCI; Manufacturer Part Number 1: 10118194-0001LF; MCHP-ID: CON1383; Symbol: CON USB2.0 Mini_Micro; Description_: CON USB2.0 MICRO-B FEMALE TH/SMD R/A; Dev Tools Status: Production; Owner: Jamus Griego; Populated: YES
J9 = CON0148: Manufacturer 1: Wurth Electronics Inc; Manufacturer Part Number 1: 61300411121; Description_: CON HDR-2.54 Male 1x4 Gold 5.84MH TH VERT; Dev Tools Status: Production; Populated: Yes
J11 J12 = CON1626: Manufacturer 1: Wurth Electronics Inc.; Manufacturer Part Number 1: 691137710003; Value: TERMINAL 1x3; Description_: CON TERMINAL 5mm 1x3 Female 12-30AWG 16A TH R/A; Dev Tools Status: Production; Owner: Catalin Modoran; Voltage: 300V; Current: 16A; Populated: YES
LED1-LED5 LED7 = DIODE1058: LED; Manufacturer 1: Lite-On; Manufacturer Part Number 1: LTST-C190EKT; Description_: DIO LED RED 2V 30mA 2mcd Clear SMD 0603; Dev Tools Status: Production; Type: LED Single; Forward Current: 30mA; Owner: Tad Ahlvers; Populated: YES; Power: 100mW; Reverse Current: 100uA; Reverse Voltage: 5V
LED6 = DIODE1243: LED; Manufacturer 1: Stanley Electric Co                                                                               Stanley Electric Co; Manufacturer Part Number 1: PG1111C-TR; Description_: DIO LED GREEN 2.1V 20mA DIFFUSED SMD 0603; Dev Tools Status: Design; Type: LED Single; Forward Current: 20mA; Owner: Mark Loper; Populated: YES
MOV1 = RES1452: Manufacturer 1: EPCOS Inc; Description_: RES VARISTOR 275V 130J TH DISC 14mm; Dev Tools Status: Production; Voltage: 275VAC; Current: 6kA; Owner: Bogdan Popescu; Populated: YES
R1 R10 = RSMT0568: Manufacturer 1: SPC Technology; Manufacturer Part Number 1: MC0603WGF4701T5E-TC; Description_: RES TKF 4.7k 1% 1/16W SMD 0603; Dev Tools Status: Production; Voltage: 150V; Temperature Coeffcient: 100ppm/C; Power: 1/16W; Populated: Yes
R2-R5 R8 R9 R16-R25 R28 R31-R34 R36 R41 = RSMT0138: as R11 on sheet HV9901 Relay Driver_V3.0
R6 R7 = RSMT1084: Manufacturer 1: Vishay Dale; Manufacturer Part Number 1: CRCW2010499KFKEF; Description_: RES TKF 499k 1% 3/4W SMD 2010; Dev Tools Status: Production; Voltage: 400V; Temperature Coeffcient: 100ppm/C; Power: 3/4W; Owner: Bogdan Popescu; Populated: YES
R26 R27 R29 = RES1178: Manufacturer 1: Panasonic; Manufacturer Part Number 1: ERJ-3GEYJ472V; Description_: RES TKF 4.7k 5% 1/10W SMD 0603; Voltage: 75V; Temperature Coeffcient: 200ppm/C; Power: 1/10W; Populated: Yes; Dev Tools Status: Production; Owner: Bogdan P (M91398)
R30 R37 = RSMT1143: Manufacturer 1: Vishay Dale; Manufacturer Part Number 1: CRCW2512402KFKEG; Description_: RES TKF 402k 1% 1W SMD 2512; Dev Tools Status: Design; Voltage: 500V; Temperature Coeffcient: 100ppm/C; Owner: Jamus Griego; Populated: YES
R40 = RES2320: as R39 on sheet HV9901 Relay Driver_V3.0
RS1 = RES1247: Shunt; Manufacturer 1: Stackpole Electronics Inc; Manufacturer Part Number 1: CSNL2512FT2L00; Description_: RES SHUNT MF 0.002R 1% 2W 2512; Dev Tools Status: Production; Voltage: 200V; Temperature Coeffcient: 50ppm/C; Power: 2W; Owner: Bogdan P (M91398); Populated: Yes
SW1 = SWITCH1046: Switch; Manufacturer 1: Wurth Electronics Inc; Description_: SWITCH TACT SPST 12V 50mA PTS645SM43SMTR92 LFS SMD; Dev Tools Status: Production; Owner: Jamus Griego; Populated: YES
U1 = MIC7556: ADC; Manufacturer 1: Microchip Technology Inc; Manufacturer Part Number 1: MCP39F511A-E/MQ; Description_: MCHP ANALOG ENERGY MEASUREMENT 4000:1 MCP39F511A-E/MQ QFN-28; MAPS Description: Single-Phase, Dual-Mode(AC/DC) PMIC w/ Calculation & Energy Accumulation; Dev Tools Status: Production; Owner: Bogdan Popescu; MPC: 360234P7X035; LeadContent: Pb-FREE; PackingMedia: TUBE; Stage: REL; LeadCount: 28; PackageWidth: 5x5x0.9mm; ForceMinOrderQtyMult: False; MinOrderQty: 0; TempRange: -40C to +125C; tblDeviceFamilyID: 13715; ADCResBit: 24; ADCAccuracy: 94.5; AntiTemper: No; PhaseCorrctn: Yes; noOfPGAs: 2; PGARange: 1:32; MeasurementErr: 0.1%; DynamicRange: 4000:1; VoltageRefDrift: 7
U3-U6 = IC1119: as U12 on sheet HV9901 Relay Driver_V3.0
U7 = MIC3213: MCP97XX; Manufacturer 1: Microchip; Description_: MCHP ANALOG TEMPERATURE SENSOR -40C to +150C MCP9700T-H/LT SC-70-5; MAPS Description: Linear Active Thermister (TM) IC (10mV/oC); Dev Tools Status: Production; MPC: GBAT1QB4XA00; LeadContent: Pb-FREE; PackingMedia: T/R; Stage: REL; LeadCount: 5; ForceMinOrderQtyMult: True; TempRange: -40C to +150C; tblDeviceFamilyID: 1068; Comments: Low cost; VccRangeMax: 5.5; VccRangeMin: 2.3; SensorOutput: Analog; TypicalAccuracy: 1; MaxAccuracy_25C: 4; MaxSupplyCurrent: 6; Slope: 10; Offset: 500; Populated: Yes
U8 = MIC0507: OPAMP; Manufacturer 1: Microchip; Description_: MCHP ANALOG OPAMP 1-Ch 10MHz MCP6021T-E/OT SOT-23-5; MAPS Description: Single 2.5V 10 MHz OP, E temp; Dev Tools Status: Production; MPC: A7CD1YC7XA00; LeadContent: Pb-FREE; PackingMedia: T/R; Stage: REL; LeadCount: 5; ForceMinOrderQtyMult: True; TempRange: -40C to +125C; tblDeviceFamilyID: 267; VDDmax: 5.5; VDDmin: 2.5; Comments: Mid-supply Internal VREF; IqMax: 1350; VosMax: 250; Amplifiers: 1; GBWP_KHz: 10000; Populated: Yes
U9 = MIC6971: Manufacturer 1: Microchip Technology; Manufacturer Part Number 1: MCP2221A-I/ML; Description_: MCHP INTERFACE USB I2C/UART MCP2221A-I/ML QFN-16; Dev Tools Status: Design; Owner: Razvan Cristescu; Populated: YES
U10 = IC1047: Bi-Directional Logic Gate Optocoupler (Fairchild); Manufacturer 1: Fairchild Semiconductor; MCHP-ID: IC1047; Description_: IC PHOTO FOD8012 Bi-Dir 3.3V and 5V SOIC-8; Dev Tools Status: Production; Vin: 3.3V~5V; Owner: Bogdan Popescu; Populated: YES
U11 = MIC5969: LDO; Manufacturer 1: Microchip Technology; Description_: MCHP ANALOG LDO 3.3V MCP1754ST-3302E/MB SOT-89-3; MAPS Description: 16v, High PSRR, 150mA LDO, Vout=3.3V; Dev Tools Status: Production; Owner: Bogdan P (M91398); MPC: V0AB2YA5XB00; LeadContent: Pb-FREE; PackingMedia: T/R; Stage: REL; LeadCount: 3; ForceMinOrderQtyMult: True; MinOrderQty: 1; TempRange: -40C to +125C; tblDeviceFamilyID: 3163; Populated: YES
Z1 = DIODE1054: Manufacturer 1: Micro Commercial Co; Manufacturer Part Number 1: SMAZ5V6-TP; Description_: DIO ZNR SMAZ5V6 5.6V 1W 5% DO-214AC_SMA; Dev Tools Status: Design; Reverse Current: 5uA; Reverse Voltage: 2V; Owner: Mike Ragsdale; Populated: YES

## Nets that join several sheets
GND: HV9901 Relay Driver_V3.0 (17 pins), MCP39F511A Power Monitoring_V3.0 (R40.1)
L-IN: HV9901 Relay Driver_V3.0 (B1.1 K1.6), MCP39F511A Power Monitoring_V3.0 (F1.1 FB3.1 MOV1.2)
L-OUT: HV9901 Relay Driver_V3.0 (K1.2), MCP39F511A Power Monitoring_V3.0 (J12.3)
N-IN: HV9901 Relay Driver_V3.0 (B1.2 K1.5), MCP39F511A Power Monitoring_V3.0 (MOV1.1 RS1.1)
N-OUT: HV9901 Relay Driver_V3.0 (K1.1), MCP39F511A Power Monitoring_V3.0 (J12.1)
